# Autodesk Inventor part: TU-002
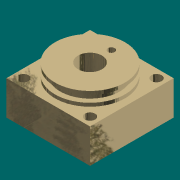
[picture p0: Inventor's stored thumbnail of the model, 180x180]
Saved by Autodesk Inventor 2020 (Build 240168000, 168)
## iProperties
Created: 2008-05
Part Number: TU-002
Document SubType Name: Modeling
Designer: PN
Density: 7.86 g/cm^3
Material: Steel, Mild
Description: Cylinder Head Cover_Front
Mass: 394.415 g
Surface Area: 129.648 cm^2
Volume: 50.1801 cm^3
Appearance: Titanium - Polished
Author: PN
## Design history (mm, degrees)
sketch "Sketch1"
  geometry: L1 (-24.5, 24.5)-(24.5, 24.5); L2 (24.5, 24.5)-(24.5, -24.5); L3 (24.5, -24.5)-(-24.5, -24.5); L4 (-24.5, -24.5)-(-24.5, 24.5); 3 further points
  constraints: 8 end point, 2 midpoint, 2 parallel, 1 horizontal, 1 horizontal alignment, 1 perpendicular, 1 vertical alignment
  dimensions: "Width" = 49 distance of L1.start L1.end; "Height" = 49 distance of L3.end L1.start (= Width)
extrude "Extrusion1" new body sketch "Sketch1" distance "d2" = 20; taper "d3" = 0 deg
sketch "Sketch2"
  geometry: L1 (24.5, 24.5)-(24.5, -24.5) reference; L2 (-24.5, 24.5)-(24.5, 24.5) reference; L3 (-24.5, -24.5)-(-24.5, 24.5) reference; L4 (24.5, -24.5)-(-24.5, -24.5) reference; L5 (19.5, 19.5)-(19.5, -19.5); L6 (19.5, -19.5)-(-19.5, -19.5); L7 (-19.5, -19.5)-(-19.5, 19.5); L8 (-19.5, 19.5)-(19.5, 19.5); 1 further point
  constraints: 8 end point, 3 other
  dimensions: "d4" = 5 distance between parallel lines of L7 L3; "d5" = 39 distance of L5.end L6.end (derived); "d6" = 39 distance of L6.end L7.end (derived)
hole "Hole1" sketch "Sketch2" at (-19.5, -19.5) diameter "d7" = 6; stored, may be unused: countersink angle "d11" = 90 deg, drill point angle "d13" = 118 deg; dims "d8" = 6, "d9" = 4, "d10" = 2, "d12" = 8
pattern_linear "Rectangular Pattern1" dims "d16" = 39 (= d5), "d19" = 39 (= d6)
sketch "Sketch3"
  geometry: L1 (-24.5, 20)-(24.5, 20) reference; L2 (0, 20)-(0, 28); L3 (0, 28)-(20.5, 28); L4 (20.5, 28)-(20.5, 26); L5 (20.5, 26)-(17.5, 26); L6 (17.5, 26)-(17.5, 22); L7 (17.5, 22)-(20.5, 22); L8 (20.5, 22)-(20.5, 20); 1 further point
  constraints: 14 end point, 4 perpendicular, 2 collinear, 2 parallel, 1 midpoint, 1 point on line
  dimensions: "d25" = 8 distance of L2.start L2.end; "d26" = 20.5 distance of L2.end L3.end; "d27" = 2 distance of L3.end L4.end; "d28" = 4 distance of L5.end L6.end; "d29" = 17.5 distance between parallel lines of L6 L2
revolve "Revolution1" sketch "Sketch3" stored, may be unused: angle "d30" = 90 deg
sketch "Sketch4"
  geometry: L1 (0, -20)-(49, -20) reference; L2 (0, 0)-(0, -20) reference; L3 (24.5, -20)-(24.5, -10); 1 further point
  constraints: 2 end point, 1 midpoint, 1 parallel
  dimensions: "d31" = 10 distance of L3.start L3.end
hole "Hole4" sketch "Sketch4" at (24.5, -10) diameter "d48" = 4.134; stored, may be unused: countersink angle "d52" = 90 deg, drill point angle "d54" = 118 deg; dims "d49" = 6, "d50" = 4, "d51" = 2, "d53" = 14
workplane "Work Plane3"
  workaxis "Work Axis2"
sketch "Sketch7"
  geometry: L1 (0, 0)-(0, 12.5); C1 r 20.5 at (0, 0) reference; 1 further point
  constraints: 2 end point, 1 coincident, 1 vertical
  dimensions: "d56" = 12.5 distance of L1.start L1.end
hole "Hole5" sketch "Sketch7" at (0, 12.5) diameter "d57" = 4; stored, may be unused: countersink angle "d61" = 90 deg, drill point angle "d63" = 118 deg; dims "d58" = 6, "d59" = 4, "d60" = 2, "d62" = 14
hole "Hole6" diameter "d66" = 14; stored, may be unused: countersink angle "d70" = 90 deg, drill point angle "d72" = 118 deg; dims "d64" = 10, "d65" = 10, "d67" = 6, "d68" = 4, "d69" = 2, "d71" = 14
body "Solid1"
other parameters: "d55" = 0
